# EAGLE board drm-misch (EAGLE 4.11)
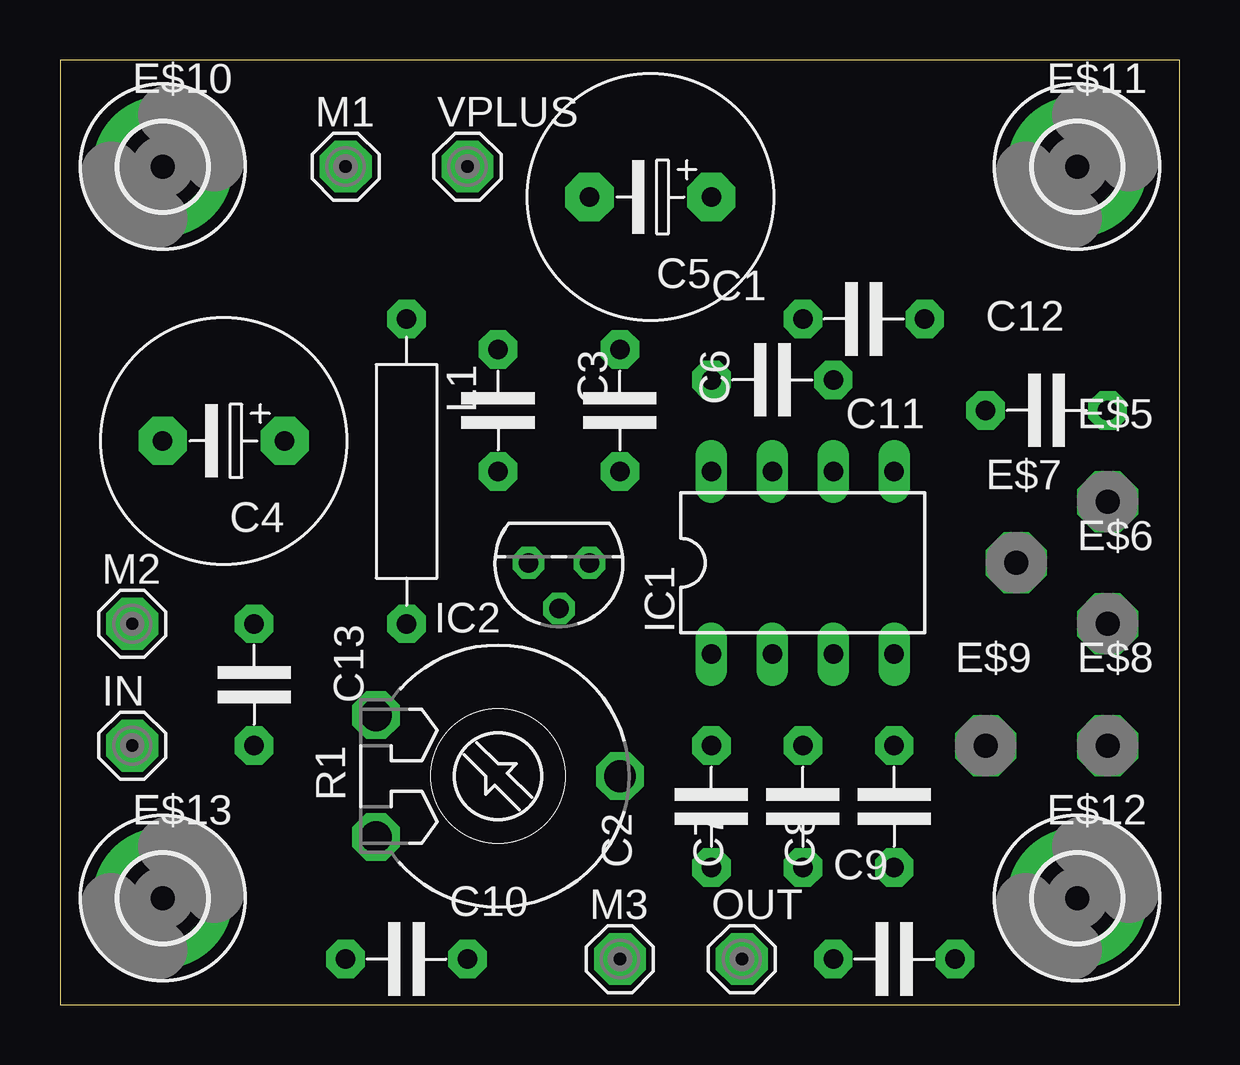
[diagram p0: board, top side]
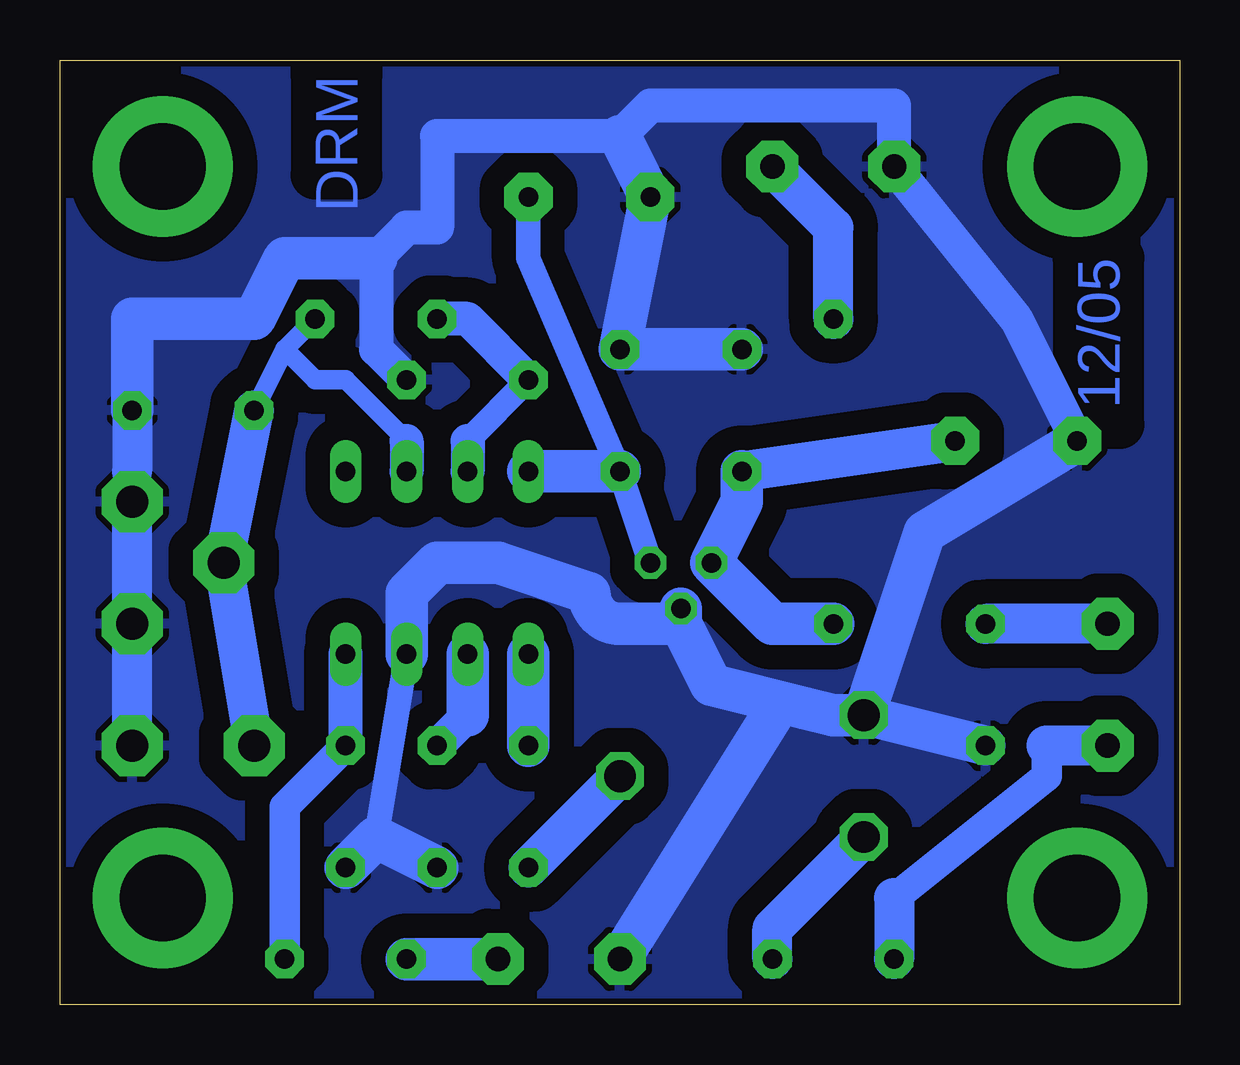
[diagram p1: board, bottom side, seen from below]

Size 46.66 x 39.36 mm. Coordinates in mm from the lower left corner, seen from the top.
Outline: 0,0 46.66,0 46.66,39.36 0,39.36 0,0
Copper layers (1*16): Top 0.035mm / dielectric 1.5mm / Bottom 0.035mm
Design rules "default": minimum track width 10mil, minimum drill 24mil, track to track 40mil, track to pad 40mil, pad to pad 16mil, via to via 8mil, smd to smd 8mil, copper to edge 10mil, drill to drill 8mil, minimum pad ring 10mil, minimum via ring 8mil, stop-mask expansion 4mil, vias tented up to drill 0mil, thermal gap 10mil

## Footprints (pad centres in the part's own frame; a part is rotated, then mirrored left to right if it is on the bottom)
C-5 = drill 0.813 pad 1.6 octagon: 1 -2.54,0; 2 2.54,0
ES-5 = drill 0.813 pad 2.007 octagon: 1 -2.54,0; 2 2.54,0
3,6-PAD = drill 3.6 pad 5.842 round: B3,6 0,0
PAD-01 = drill 1.321 pad 2.54 octagon: 1 0,0
DIL08 = drill 0.813 long: 1 -3.81,-3.81; 2 -1.27,-3.81; 3 1.27,-3.81; 4 3.81,-3.81; 5 3.81,3.81; 6 1.27,3.81; 7 -1.27,3.81; 8 -3.81,3.81
TO92 = drill 0.813 octagon: 1 -1.27,0; 2 0,1.905; 3 1.27,0
MCS10B = drill 1.016 pad 2.159 octagon: MP 0,0
L-12,5 = drill 0.813 pad 1.6 octagon: 1 -6.35,0; 2 6.35,0
LI10 = drill 1.321 octagon: A -2.54,-5.08; E 2.54,-5.08; S 0,5.08

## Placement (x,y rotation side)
C1  2n2  [C-5]  29.68,26.03 0 top
C2  [C-5]  27.14,8.25 90 top
C3  10 uF  [C-5]  18.25,24.76 270 top
C4  10 uF  [ES-5]  6.82,23.49 180 top
C5  10 uF  [ES-5]  24.6,33.65 180 top
C6  100 nF  [C-5]  23.33,24.76 270 top
C7  100 nF  [C-5]  30.95,8.25 90 top
C8  2n2  [C-5]  34.76,8.25 90 top
C9  100 nF  [C-5]  34.76,1.9 0 top
C10  100 nF  [C-5]  14.44,1.9 180 top
C11  2n2  [C-5]  33.49,28.57 180 top
C12  220 pF  [C-5]  41.11,24.76 0 top
C13  100 nF  [C-5]  8.09,13.33 270 top
E$1  [3,6-PAD]  4.28,34.92 0 top
E$2  [3,6-PAD]  42.38,34.92 0 top
E$3  [3,6-PAD]  42.38,4.44 0 top
E$4  [3,6-PAD]  4.28,4.44 0 top
E$5  [PAD-01]  43.65,20.95 0 top
E$6  [PAD-01]  43.65,15.87 0 top
E$7  [PAD-01]  39.84,18.41 0 top
E$8  [PAD-01]  43.65,10.79 0 top
E$9  [PAD-01]  38.57,10.79 0 top
E$10  [PAD-01]  4.28,34.92 0 top
E$11  [PAD-01]  42.38,34.92 0 top
E$12  [PAD-01]  42.38,4.44 0 top
E$13  [PAD-01]  4.28,4.44 0 top
IC1  NE602  [DIL08]  30.95,18.41 0 top
IC2  7806L  [TO92]  20.79,18.41 180 top
IN  [MCS10B]  3.01,10.79 0 top
L1  100 uH  [L-12,5]  14.44,22.22 270 top
M1  [MCS10B]  11.9,34.92 0 top
M2  [MCS10B]  3.01,15.87 0 top
M3  [MCS10B]  23.33,1.9 0 top
OUT  [MCS10B]  28.41,1.9 0 top
R1  5 k  [LI10]  18.25,9.52 270 top
VPLUS  VPLUS  [MCS10B]  16.98,34.92 0 top

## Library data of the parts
C1-C13 E$5-E$13 L1 = discrete
E$1-E$4 = holes
IC1 = ic-package
IC2 = linear
IN M1-M3 OUT VPLUS = solpad
R1 = pot

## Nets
GND: C1.2 C3.1 C4.2 C5.2 C6.1 C7.1 C8.1 C12.2 C13.2 E$5.1 E$6.1 E$8.1 IC1.3 IC2.2 M1.MP M3.MP R1.A
N$1: C2.2 IC1.1
N$2: C2.1 R1.S
N$3: C6.2 IC1.8 IC2.1
N$4: C3.2 C4.1 IC2.3 L1.2
N$5: C7.2 IC1.2
N$6: C10.1 R1.E
N$7: C8.2 C9.2 IC1.4
N$8: C1.1 C11.2 IC1.7
N$9: C11.1 C12.1 E$7.1 E$9.1 IC1.6
S$1: C13.1 M2.MP
S$2: C9.1 OUT.MP
S$3: C10.2 IN.MP
S$4: L1.1 VPLUS.MP

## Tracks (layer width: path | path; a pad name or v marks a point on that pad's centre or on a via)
GND
  Bottom 1.016: IC1.3 33.49,6.98
  Bottom 1.422: C1.2 33.49,27.3 33.49,31.11 32.22,32.38 30.95,32.38 30.95,36.19 23.33,36.19 22.06,37.46 11.9,37.46 M1.MP 6.82,28.57 C4.2
  Bottom 1.676: C13.2 R1.A | C12.2 43.65,22.22 | E$5.1 E$6.1 E$8.1
  Bottom 1.778: C12.2 43.65,28.57 38.57,28.57 37.3,31.11 33.49,31.11 | C3.1 C6.1 C5.2 23.33,36.19 | C8.1 33.49,6.98 C7.1 | IC1.3 32.22,17.14 30.95,18.41 28.41,18.41 24.6,17.14 arc-90 23.33,15.87 20.79,15.87 | C4.2 10.63,19.68 R1.A 14.44,12.06 15.64,12.36 19.52,13.33 20.79,15.87 | 20.79,15.87 IC2.2 | M3.MP 16.98,12.06
  pour Bottom: -0.8,41.27 -0.8,-1.91 48.73,-1.91 48.73,41.27
N$1
  Bottom 1.778: C2.2 IC1.1
N$2
  Bottom 1.676: C2.1 R1.S
N$3
  Bottom 1.016: 27.14,33.65 27.14,31.11 C6.2 IC2.1
  Bottom 1.778: C6.2 IC1.8
N$4
  Bottom 1.676: C3.2 C4.1
  Bottom 1.778: C3.2 18.25,20.95 IC2.3 16.98,15.87 L1.2
N$5
  Bottom 1.422: C7.2 29.68,12.06
  Bottom 1.778: 29.68,12.06 IC1.2
N$6
  Bottom 1.676: R1.E 16.98,3.17 C10.1
N$7
  Bottom 1.27: C8.2 37.3,8.25 C9.2
  Bottom 1.422: C8.2 IC1.4
N$8
  Bottom 1.016: C1.1 29.68,23.49
  Bottom 1.422: 29.68,23.49 IC1.7 | C11.2 29.68,28.57 C1.1
N$9
  Bottom 0.813: 37.3,27.3 C11.1 | C12.1 37.3,27.3 | 37.3,27.3 36.03,26.03 34.76,26.03 32.22,23.49
  Bottom 1.422: 32.22,23.49 IC1.6
  Bottom 1.676: C12.1 E$7.1 E$9.1
S$1
  Bottom 1.676: M2.MP C13.1
S$2
  Bottom 1.778: OUT.MP C9.1
S$3
  Bottom 1.27: 5.55,10.79 5.55,9.52 11.9,4.44
  Bottom 1.676: 11.9,4.44 C10.2 | IN.MP 5.55,10.79
S$4
  Bottom 1.676: L1.1 14.44,32.38 VPLUS.MP

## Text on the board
Bottom: DRM | 12/05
